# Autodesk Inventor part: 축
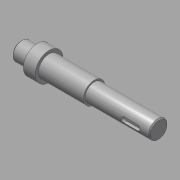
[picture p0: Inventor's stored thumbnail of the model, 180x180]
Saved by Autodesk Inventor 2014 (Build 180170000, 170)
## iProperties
Created: 2015-09
Part Number: 축
Material: 강철, 연강
Document SubType Name: Modeling
Designer: mduedu
Density: 7.86 g/cm^3
Mass: 263.424 g
Surface Area: 86.4309 cm^2
Volume: 33.5145 cm^3
Appearance: Steel
Author: mduedu
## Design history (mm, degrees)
sketch "스케치1"
  geometry: L1 (-69, 0)-(69, 0); L2 (-69, 0)-(-69, 8.5); L3 (-69, 8.5)-(-54, 8.5); L4 (-54, 8.5)-(-54, 13); L5 (-54, 13)-(-43, 13); L6 (-43, 13)-(-43, 10); L7 (-43, 10)-(-1, 10); L8 (-1, 10)-(-1, 8.5); L9 (-1, 8.5)-(69, 8.5); L10 (69, 8.5)-(69, 0); 2 further points
  constraints: 20 end point, 5 parallel, 2 horizontal, 2 perpendicular, 1 coincident, 1 midpoint, 1 vertical
  dimensions: "d0" = 138 distance of L1.start L1.end; "d2" = 11 distance of L4.end L5.end; "d3" = 42 distance of L6.end L7.end; "d4" = 70 distance of L8.end L9.end; "d5" = 17 diameter of L3 L1; "d6" = 17 diameter of L9 L1; "d7" = 20 diameter of L7 L1; "d8" = 26 diameter of L5 L1
revolve "회전1" sketch "스케치1" stored, may be unused: angle "d9" = 90 deg
node "작업 평면1"
sketch "스케치2"
  geometry: L1 (10.5, 2.5)-(23.5, 2.5); L2 (23.5, -2.5)-(10.5, -2.5); L3 (10.5, 2.5)-(23.5, -2.5); L4 (23.5, 2.5)-(10.5, -2.5); L5 (35, -8.5)-(35, 8.5) reference; A1 r 2.5 centre (10.5, 0) between (10.5, 2.5) and (10.5, -2.5); A2 r 2.5 centre (23.5, 0) between (23.5, -2.5) and (23.5, 2.5); 2 further points
  constraints: 8 end point, 4 point on circle, 4 tangent, 2 centre point, 2 midpoint, 1 horizontal, 1 horizontal alignment, 1 parallel
  dimensions: "d10" = 18 dimension on A2 A1; "d12" = 9 distance edge to line of A2 L5; "d13" = 5 distance between parallel lines of L2 L1
extrude "돌출1" cut sketch "스케치2" distance "d14" = 3; taper "d15" = 0 deg
node "작업 평면2"
sketch "스케치4"
  geometry: L1 (7, -3)-(-9, -3); L2 (-9, 3)-(7, 3); L3 (-21, 10)-(-21, -10) reference; A1 r 3 centre (-9, 0) between (-9, 3) and (-9, -3); A2 r 3 centre (7, 0) between (7, -3) and (7, 3); 1 further point
  constraints: 4 end point, 4 point on circle, 4 tangent, 2 centre point, 1 horizontal, 1 horizontal alignment, 1 parallel
  dimensions: "d16" = 22 dimension on A1 A2; "d18" = 6 distance between parallel lines of L2 L1; "d19" = 9 distance edge to line of A1 L3
extrude "돌출2" cut sketch "스케치4" distance "d20" = 3.5; taper "d21" = 0 deg
sketch "스케치5"
  geometry: L1 (-1, 8.5)-(69, 8.5) reference; L2 (-1, -8.5)-(69, -8.5) reference; L3 (42, 8.5)-(42, -8.5); L4 (42, -6.5)-(40, -8.5); L5 (42, -8.5)-(40, -8.5); L6 (42, -8.5)-(42, -6.5); L7 (-1, -10)-(-1, 10) reference; 1 further point
  constraints: 8 end point, 4 point on line, 1 collinear, 1 perpendicular
  dimensions: "d22" = 4 diameter of L4.end L3; "d24" = 45 deg angle of L3 L4; "d26" = 43 distance between parallel lines of L3 L7
revolve "회전2" sketch "스케치5" stored, may be unused: angle "d27" = 90 deg
chamfer "모따기1" distance "d28" = 1; stored, may be unused: second distance "d29" = 2, angle "d30" = 45 deg
sketch "스케치6"
  geometry: L1 (42, -6.5)-(40, -8.5) reference; L2 (42, -6.5)-(44, -8.5) reference; 2 further points
  constraints: 1 coincident
node "솔리드1"
